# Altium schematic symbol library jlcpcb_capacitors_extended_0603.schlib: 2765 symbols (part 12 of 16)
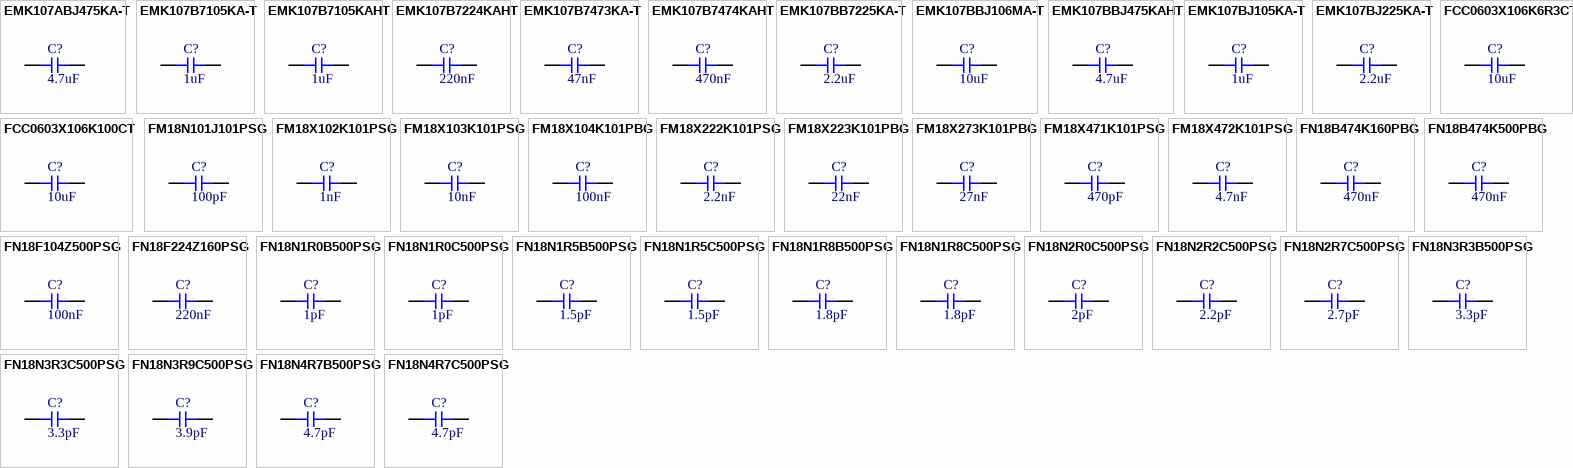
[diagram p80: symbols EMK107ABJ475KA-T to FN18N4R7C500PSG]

## FM18X471K101PSG
designator C?  Capacitance: 470pF  (hidden comment: *)
Capacitor, Ceramic (MLCC), 470pF, ±10%, 100V, X7R, ±10%, SMD 0603; Manufacturer: PSA(Prosperity Dielectrics); Manufacturer Part Number: FM18X471K101PSG
footprint CAP-0603 (0603 (1608M) Capacitor)
pins: 1, 2

## FM18X472K101PSG
designator C?  Capacitance: 4.7nF  (hidden comment: *)
Capacitor, Ceramic (MLCC), 4.7nF, ±10%, 100V, X7R, ±10%, SMD 0603; Manufacturer: PSA(Prosperity Dielectrics); Manufacturer Part Number: FM18X472K101PSG
footprint CAP-0603 (0603 (1608M) Capacitor)
pins: 1, 2

## FN18B474K160PBG
designator C?  Capacitance: 470nF  (hidden comment: *)
Capacitor, Ceramic (MLCC), 470nF, ±10%, 16V, X5R, ±10%, SMD 0603; Manufacturer: PSA(Prosperity Dielectrics); Manufacturer Part Number: FN18B474K160PBG
footprint CAP-0603 (0603 (1608M) Capacitor)
pins: 1, 2

## FN18B474K500PBG
designator C?  Capacitance: 470nF  (hidden comment: *)
Capacitor, Ceramic (MLCC), 470nF, ±10%, 50V, X5R, ±10%, SMD 0603; Manufacturer: PSA(Prosperity Dielectrics); Manufacturer Part Number: FN18B474K500PBG
footprint CAP-0603 (0603 (1608M) Capacitor)
pins: 1, 2

## FN18F104Z500PSG
designator C?  Capacitance: 100nF  (hidden comment: *)
Capacitor, Ceramic (MLCC), 100nF, 50V, Y5V, SMD 0603; Manufacturer: PSA(Prosperity Dielectrics); Manufacturer Part Number: FN18F104Z500PSG; Temperature Rating: -20%~+80%
footprint CAP-0603 (0603 (1608M) Capacitor)
pins: 1, 2

## FN18F224Z160PSG
designator C?  Capacitance: 220nF  (hidden comment: *)
Capacitor, Ceramic (MLCC), 220nF, 16V, Y5V, SMD 0603; Manufacturer: PSA(Prosperity Dielectrics); Manufacturer Part Number: FN18F224Z160PSG; Temperature Rating: -20%~+80%
footprint CAP-0603 (0603 (1608M) Capacitor)
pins: 1, 2

## FN18N1R0B500PSG
designator C?  Capacitance: 1pF  (hidden comment: *)
Capacitor, Ceramic (MLCC), 1pF, ±0.1pF, 50V, NP0, ±0.1pF, SMD 0603; Manufacturer: PSA(Prosperity Dielectrics); Manufacturer Part Number: FN18N1R0B500PSG
footprint CAP-0603 (0603 (1608M) Capacitor)
pins: 1, 2

## FN18N1R0C500PSG
designator C?  Capacitance: 1pF  (hidden comment: *)
Capacitor, Ceramic (MLCC), 1pF, ±0.25pF, 50V, C0G, ±0.25pF, SMD 0603; Manufacturer: PSA(Prosperity Dielectrics); Manufacturer Part Number: FN18N1R0C500PSG
footprint CAP-0603 (0603 (1608M) Capacitor)
pins: 1, 2

## FN18N1R5B500PSG
designator C?  Capacitance: 1.5pF  (hidden comment: *)
Capacitor, Ceramic (MLCC), 1.5pF, ±0.1pF, 50V, NP0, ±0.1pF, SMD 0603; Manufacturer: PSA(Prosperity Dielectrics); Manufacturer Part Number: FN18N1R5B500PSG
footprint CAP-0603 (0603 (1608M) Capacitor)
pins: 1, 2

## FN18N1R5C500PSG
designator C?  Capacitance: 1.5pF  (hidden comment: *)
Capacitor, Ceramic (MLCC), 1.5pF, ±0.25pF, 50V, C0G, ±0.25pF, SMD 0603; Manufacturer: PSA(Prosperity Dielectrics); Manufacturer Part Number: FN18N1R5C500PSG
footprint CAP-0603 (0603 (1608M) Capacitor)
pins: 1, 2

## FN18N1R8B500PSG
designator C?  Capacitance: 1.8pF  (hidden comment: *)
Capacitor, Ceramic (MLCC), 1.8pF, ±0.1pF, 50V, NP0, ±0.1pF, SMD 0603; Manufacturer: PSA(Prosperity Dielectrics); Manufacturer Part Number: FN18N1R8B500PSG
footprint CAP-0603 (0603 (1608M) Capacitor)
pins: 1, 2

## FN18N1R8C500PSG
designator C?  Capacitance: 1.8pF  (hidden comment: *)
Capacitor, Ceramic (MLCC), 1.8pF, ±0.25pF, 50V, C0G, ±0.25pF, SMD 0603; Manufacturer: PSA(Prosperity Dielectrics); Manufacturer Part Number: FN18N1R8C500PSG
footprint CAP-0603 (0603 (1608M) Capacitor)
pins: 1, 2

## FN18N2R0C500PSG
designator C?  Capacitance: 2pF  (hidden comment: *)
Capacitor, Ceramic (MLCC), 2pF, ±0.25pF, 50V, C0G, ±0.25pF, SMD 0603; Manufacturer: PSA(Prosperity Dielectrics); Manufacturer Part Number: FN18N2R0C500PSG
footprint CAP-0603 (0603 (1608M) Capacitor)
pins: 1, 2

## FN18N2R2C500PSG
designator C?  Capacitance: 2.2pF  (hidden comment: *)
Capacitor, Ceramic (MLCC), 2.2pF, ±0.25pF, 50V, NP0, ±0.25pF, SMD 0603; Manufacturer: PSA(Prosperity Dielectrics); Manufacturer Part Number: FN18N2R2C500PSG
footprint CAP-0603 (0603 (1608M) Capacitor)
pins: 1, 2

## FN18N2R7C500PSG
designator C?  Capacitance: 2.7pF  (hidden comment: *)
Capacitor, Ceramic (MLCC), 2.7pF, ±0.25pF, 50V, NP0, ±0.25pF, SMD 0603; Manufacturer: PSA(Prosperity Dielectrics); Manufacturer Part Number: FN18N2R7C500PSG
footprint CAP-0603 (0603 (1608M) Capacitor)
pins: 1, 2

## FN18N3R3B500PSG
designator C?  Capacitance: 3.3pF  (hidden comment: *)
Capacitor, Ceramic (MLCC), 3.3pF, ±0.1pF, 50V, NP0, ±0.1pF, SMD 0603; Manufacturer: PSA(Prosperity Dielectrics); Manufacturer Part Number: FN18N3R3B500PSG
footprint CAP-0603 (0603 (1608M) Capacitor)
pins: 1, 2

## FN18N3R3C500PSG
designator C?  Capacitance: 3.3pF  (hidden comment: *)
Capacitor, Ceramic (MLCC), 3.3pF, ±0.25pF, 50V, C0G, ±0.25pF, SMD 0603; Manufacturer: PSA(Prosperity Dielectrics); Manufacturer Part Number: FN18N3R3C500PSG
footprint CAP-0603 (0603 (1608M) Capacitor)
pins: 1, 2

## FN18N3R9C500PSG
designator C?  Capacitance: 3.9pF  (hidden comment: *)
Capacitor, Ceramic (MLCC), 3.9pF, ±0.25pF, 50V, C0G, ±0.25pF, SMD 0603; Manufacturer: PSA(Prosperity Dielectrics); Manufacturer Part Number: FN18N3R9C500PSG
footprint CAP-0603 (0603 (1608M) Capacitor)
pins: 1, 2

## FN18N4R7B500PSG
designator C?  Capacitance: 4.7pF  (hidden comment: *)
Capacitor, Ceramic (MLCC), 4.7pF, ±0.1pF, 50V, NP0, ±0.1pF, SMD 0603; Manufacturer: PSA(Prosperity Dielectrics); Manufacturer Part Number: FN18N4R7B500PSG
footprint CAP-0603 (0603 (1608M) Capacitor)
pins: 1, 2

## FN18N4R7C500PSG
designator C?  Capacitance: 4.7pF  (hidden comment: *)
Capacitor, Ceramic (MLCC), 4.7pF, ±0.25pF, 50V, C0G, ±0.25pF, SMD 0603; Manufacturer: PSA(Prosperity Dielectrics); Manufacturer Part Number: FN18N4R7C500PSG
footprint CAP-0603 (0603 (1608M) Capacitor)
pins: 1, 2

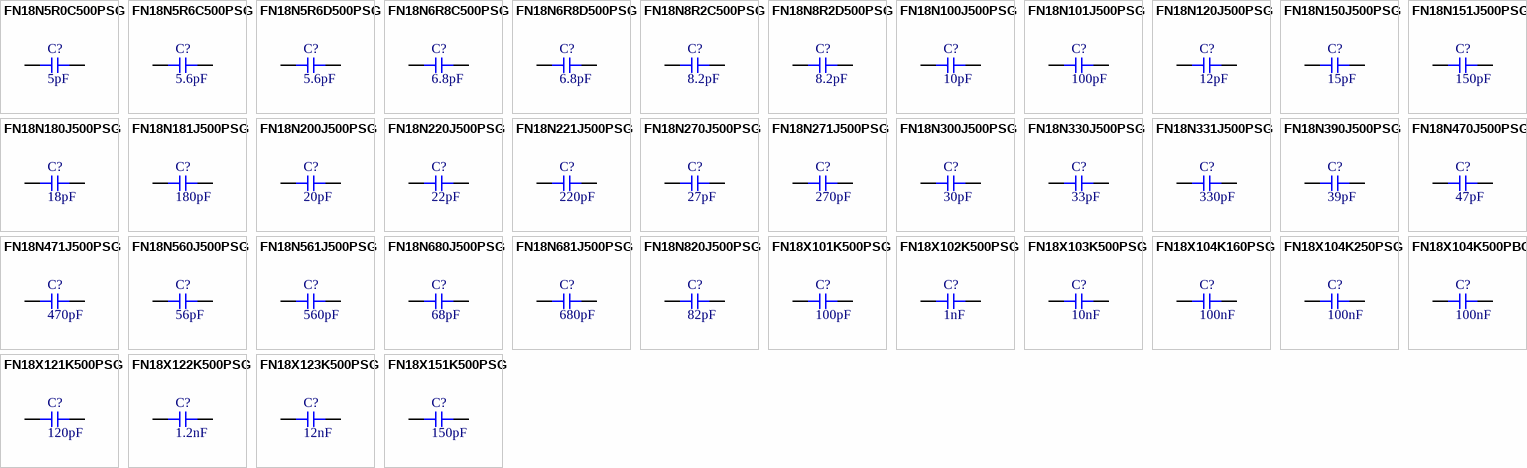
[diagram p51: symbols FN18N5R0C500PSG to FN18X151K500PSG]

## FN18N5R0C500PSG
designator C?  Capacitance: 5pF  (hidden comment: *)
Capacitor, Ceramic (MLCC), 5pF, ±0.25pF, 50V, C0G, ±0.25pF, SMD 0603; Manufacturer: PSA(Prosperity Dielectrics); Manufacturer Part Number: FN18N5R0C500PSG
footprint CAP-0603 (0603 (1608M) Capacitor)
pins: 1, 2

## FN18N5R6C500PSG
designator C?  Capacitance: 5.6pF  (hidden comment: *)
Capacitor, Ceramic (MLCC), 5.6pF, ±0.25pF, 50V, C0G, ±0.25pF, SMD 0603; Manufacturer: PSA(Prosperity Dielectrics); Manufacturer Part Number: FN18N5R6C500PSG
footprint CAP-0603 (0603 (1608M) Capacitor)
pins: 1, 2

## FN18N5R6D500PSG
designator C?  Capacitance: 5.6pF  (hidden comment: *)
Capacitor, Ceramic (MLCC), 5.6pF, ±0.5pF, 50V, C0G, ±0.5pF, SMD 0603; Manufacturer: PSA(Prosperity Dielectrics); Manufacturer Part Number: FN18N5R6D500PSG
footprint CAP-0603 (0603 (1608M) Capacitor)
pins: 1, 2

## FN18N6R8C500PSG
designator C?  Capacitance: 6.8pF  (hidden comment: *)
Capacitor, Ceramic (MLCC), 6.8pF, ±0.25pF, 50V, NP0, ±0.25pF, SMD 0603; Manufacturer: PSA(Prosperity Dielectrics); Manufacturer Part Number: FN18N6R8C500PSG
footprint CAP-0603 (0603 (1608M) Capacitor)
pins: 1, 2

## FN18N6R8D500PSG
designator C?  Capacitance: 6.8pF  (hidden comment: *)
Capacitor, Ceramic (MLCC), 6.8pF, ±0.5pF, 50V, C0G, ±0.5pF, SMD 0603; Manufacturer: PSA(Prosperity Dielectrics); Manufacturer Part Number: FN18N6R8D500PSG
footprint CAP-0603 (0603 (1608M) Capacitor)
pins: 1, 2

## FN18N8R2C500PSG
designator C?  Capacitance: 8.2pF  (hidden comment: *)
Capacitor, Ceramic (MLCC), 8.2pF, ±0.25pF, 50V, C0G, ±0.25pF, SMD 0603; Manufacturer: PSA(Prosperity Dielectrics); Manufacturer Part Number: FN18N8R2C500PSG
footprint CAP-0603 (0603 (1608M) Capacitor)
pins: 1, 2

## FN18N8R2D500PSG
designator C?  Capacitance: 8.2pF  (hidden comment: *)
Capacitor, Ceramic (MLCC), 8.2pF, ±0.5pF, 50V, C0G, ±0.5pF, SMD 0603; Manufacturer: PSA(Prosperity Dielectrics); Manufacturer Part Number: FN18N8R2D500PSG
footprint CAP-0603 (0603 (1608M) Capacitor)
pins: 1, 2

## FN18N100J500PSG
designator C?  Capacitance: 10pF  (hidden comment: *)
Capacitor, Ceramic (MLCC), 10pF, ±5%, 50V, NP0, ±5%, SMD 0603; Manufacturer: PSA(Prosperity Dielectrics); Manufacturer Part Number: FN18N100J500PSG
footprint CAP-0603 (0603 (1608M) Capacitor)
pins: 1, 2

## FN18N101J500PSG
designator C?  Capacitance: 100pF  (hidden comment: *)
Capacitor, Ceramic (MLCC), 100pF, ±5%, 50V, NP0, ±5%, SMD 0603; Manufacturer: PSA(Prosperity Dielectrics); Manufacturer Part Number: FN18N101J500PSG
footprint CAP-0603 (0603 (1608M) Capacitor)
pins: 1, 2

## FN18N120J500PSG
designator C?  Capacitance: 12pF  (hidden comment: *)
Capacitor, Ceramic (MLCC), 12pF, ±5%, 50V, C0G, ±5%, SMD 0603; Manufacturer: PSA(Prosperity Dielectrics); Manufacturer Part Number: FN18N120J500PSG
footprint CAP-0603 (0603 (1608M) Capacitor)
pins: 1, 2

## FN18N150J500PSG
designator C?  Capacitance: 15pF  (hidden comment: *)
Capacitor, Ceramic (MLCC), 15pF, ±5%, 50V, C0G, ±5%, SMD 0603; Manufacturer: PSA(Prosperity Dielectrics); Manufacturer Part Number: FN18N150J500PSG
footprint CAP-0603 (0603 (1608M) Capacitor)
pins: 1, 2

## FN18N151J500PSG
designator C?  Capacitance: 150pF  (hidden comment: *)
Capacitor, Ceramic (MLCC), 150pF, ±5%, 50V, NP0, ±5%, SMD 0603; Manufacturer: PSA(Prosperity Dielectrics); Manufacturer Part Number: FN18N151J500PSG
footprint CAP-0603 (0603 (1608M) Capacitor)
pins: 1, 2

## FN18N180J500PSG
designator C?  Capacitance: 18pF  (hidden comment: *)
Capacitor, Ceramic (MLCC), 18pF, ±5%, 50V, C0G, ±5%, SMD 0603; Manufacturer: PSA(Prosperity Dielectrics); Manufacturer Part Number: FN18N180J500PSG
footprint CAP-0603 (0603 (1608M) Capacitor)
pins: 1, 2

## FN18N181J500PSG
designator C?  Capacitance: 180pF  (hidden comment: *)
Capacitor, Ceramic (MLCC), 180pF, ±5%, 50V, C0G, ±5%, SMD 0603; Manufacturer: PSA(Prosperity Dielectrics); Manufacturer Part Number: FN18N181J500PSG
footprint CAP-0603 (0603 (1608M) Capacitor)
pins: 1, 2

## FN18N200J500PSG
designator C?  Capacitance: 20pF  (hidden comment: *)
Capacitor, Ceramic (MLCC), 20pF, ±5%, 50V, C0G, ±5%, SMD 0603; Manufacturer: PSA(Prosperity Dielectrics); Manufacturer Part Number: FN18N200J500PSG
footprint CAP-0603 (0603 (1608M) Capacitor)
pins: 1, 2

## FN18N220J500PSG
designator C?  Capacitance: 22pF  (hidden comment: *)
Capacitor, Ceramic (MLCC), 22pF, ±5%, 50V, C0G, ±5%, SMD 0603; Manufacturer: PSA(Prosperity Dielectrics); Manufacturer Part Number: FN18N220J500PSG
footprint CAP-0603 (0603 (1608M) Capacitor)
pins: 1, 2

## FN18N221J500PSG
designator C?  Capacitance: 220pF  (hidden comment: *)
Capacitor, Ceramic (MLCC), 220pF, ±5%, 50V, C0G, ±5%, SMD 0603; Manufacturer: PSA(Prosperity Dielectrics); Manufacturer Part Number: FN18N221J500PSG
footprint CAP-0603 (0603 (1608M) Capacitor)
pins: 1, 2

## FN18N270J500PSG
designator C?  Capacitance: 27pF  (hidden comment: *)
Capacitor, Ceramic (MLCC), 27pF, ±5%, 50V, C0G, ±5%, SMD 0603; Manufacturer: PSA(Prosperity Dielectrics); Manufacturer Part Number: FN18N270J500PSG
footprint CAP-0603 (0603 (1608M) Capacitor)
pins: 1, 2

## FN18N271J500PSG
designator C?  Capacitance: 270pF  (hidden comment: *)
Capacitor, Ceramic (MLCC), 270pF, ±5%, 50V, NP0, ±5%, SMD 0603; Manufacturer: PSA(Prosperity Dielectrics); Manufacturer Part Number: FN18N271J500PSG
footprint CAP-0603 (0603 (1608M) Capacitor)
pins: 1, 2

## FN18N300J500PSG
designator C?  Capacitance: 30pF  (hidden comment: *)
Capacitor, Ceramic (MLCC), 30pF, ±5%, 50V, C0G, ±5%, SMD 0603; Manufacturer: PSA(Prosperity Dielectrics); Manufacturer Part Number: FN18N300J500PSG
footprint CAP-0603 (0603 (1608M) Capacitor)
pins: 1, 2

## FN18N330J500PSG
designator C?  Capacitance: 33pF  (hidden comment: *)
Capacitor, Ceramic (MLCC), 33pF, ±5%, 50V, C0G, ±5%, SMD 0603; Manufacturer: PSA(Prosperity Dielectrics); Manufacturer Part Number: FN18N330J500PSG
footprint CAP-0603 (0603 (1608M) Capacitor)
pins: 1, 2

## FN18N331J500PSG
designator C?  Capacitance: 330pF  (hidden comment: *)
Capacitor, Ceramic (MLCC), 330pF, ±5%, 50V, C0G, ±5%, SMD 0603; Manufacturer: PSA(Prosperity Dielectrics); Manufacturer Part Number: FN18N331J500PSG
footprint CAP-0603 (0603 (1608M) Capacitor)
pins: 1, 2

## FN18N390J500PSG
designator C?  Capacitance: 39pF  (hidden comment: *)
Capacitor, Ceramic (MLCC), 39pF, ±5%, 50V, C0G, ±5%, SMD 0603; Manufacturer: PSA(Prosperity Dielectrics); Manufacturer Part Number: FN18N390J500PSG
footprint CAP-0603 (0603 (1608M) Capacitor)
pins: 1, 2

## FN18N470J500PSG
designator C?  Capacitance: 47pF  (hidden comment: *)
Capacitor, Ceramic (MLCC), 47pF, ±5%, 50V, C0G, ±5%, SMD 0603; Manufacturer: PSA(Prosperity Dielectrics); Manufacturer Part Number: FN18N470J500PSG
footprint CAP-0603 (0603 (1608M) Capacitor)
pins: 1, 2

## FN18N471J500PSG
designator C?  Capacitance: 470pF  (hidden comment: *)
Capacitor, Ceramic (MLCC), 470pF, ±5%, 50V, C0G, ±5%, SMD 0603; Manufacturer: PSA(Prosperity Dielectrics); Manufacturer Part Number: FN18N471J500PSG
footprint CAP-0603 (0603 (1608M) Capacitor)
pins: 1, 2

## FN18N560J500PSG
designator C?  Capacitance: 56pF  (hidden comment: *)
Capacitor, Ceramic (MLCC), 56pF, ±5%, 50V, C0G, ±5%, SMD 0603; Manufacturer: PSA(Prosperity Dielectrics); Manufacturer Part Number: FN18N560J500PSG
footprint CAP-0603 (0603 (1608M) Capacitor)
pins: 1, 2

## FN18N561J500PSG
designator C?  Capacitance: 560pF  (hidden comment: *)
Capacitor, Ceramic (MLCC), 560pF, ±5%, 50V, C0G, ±5%, SMD 0603; Manufacturer: PSA(Prosperity Dielectrics); Manufacturer Part Number: FN18N561J500PSG
footprint CAP-0603 (0603 (1608M) Capacitor)
pins: 1, 2

## FN18N680J500PSG
designator C?  Capacitance: 68pF  (hidden comment: *)
Capacitor, Ceramic (MLCC), 68pF, ±5%, 50V, C0G, ±5%, SMD 0603; Manufacturer: PSA(Prosperity Dielectrics); Manufacturer Part Number: FN18N680J500PSG
footprint CAP-0603 (0603 (1608M) Capacitor)
pins: 1, 2

## FN18N681J500PSG
designator C?  Capacitance: 680pF  (hidden comment: *)
Capacitor, Ceramic (MLCC), 680pF, ±5%, 50V, NP0, ±5%, SMD 0603; Manufacturer: PSA(Prosperity Dielectrics); Manufacturer Part Number: FN18N681J500PSG
footprint CAP-0603 (0603 (1608M) Capacitor)
pins: 1, 2

## FN18N820J500PSG
designator C?  Capacitance: 82pF  (hidden comment: *)
Capacitor, Ceramic (MLCC), 82pF, ±5%, 50V, C0G, ±5%, SMD 0603; Manufacturer: PSA(Prosperity Dielectrics); Manufacturer Part Number: FN18N820J500PSG
footprint CAP-0603 (0603 (1608M) Capacitor)
pins: 1, 2

## FN18X101K500PSG
designator C?  Capacitance: 100pF  (hidden comment: *)
Capacitor, Ceramic (MLCC), 100pF, ±10%, 50V, X7R, ±10%, SMD 0603; Manufacturer: PSA(Prosperity Dielectrics); Manufacturer Part Number: FN18X101K500PSG
footprint CAP-0603 (0603 (1608M) Capacitor)
pins: 1, 2

## FN18X102K500PSG
designator C?  Capacitance: 1nF  (hidden comment: *)
Capacitor, Ceramic (MLCC), 1nF, ±10%, 50V, X7R, ±10%, SMD 0603; Manufacturer: PSA(Prosperity Dielectrics); Manufacturer Part Number: FN18X102K500PSG
footprint CAP-0603 (0603 (1608M) Capacitor)
pins: 1, 2

## FN18X103K500PSG
designator C?  Capacitance: 10nF  (hidden comment: *)
Capacitor, Ceramic (MLCC), 10nF, ±10%, 50V, X7R, ±10%, SMD 0603; Manufacturer: PSA(Prosperity Dielectrics); Manufacturer Part Number: FN18X103K500PSG
footprint CAP-0603 (0603 (1608M) Capacitor)
pins: 1, 2

## FN18X104K160PSG
designator C?  Capacitance: 100nF  (hidden comment: *)
Capacitor, Ceramic (MLCC), 100nF, ±10%, 16V, X7R, ±10%, SMD 0603; Manufacturer: PSA(Prosperity Dielectrics); Manufacturer Part Number: FN18X104K160PSG
footprint CAP-0603 (0603 (1608M) Capacitor)
pins: 1, 2

## FN18X104K250PSG
designator C?  Capacitance: 100nF  (hidden comment: *)
Capacitor, Ceramic (MLCC), 100nF, ±10%, 25V, X7R, ±10%, SMD 0603; Manufacturer: PSA(Prosperity Dielectrics); Manufacturer Part Number: FN18X104K250PSG
footprint CAP-0603 (0603 (1608M) Capacitor)
pins: 1, 2

## FN18X104K500PBG
designator C?  Capacitance: 100nF  (hidden comment: *)
Capacitor, Ceramic (MLCC), 100nF, ±10%, 50V, X7R, ±10%, SMD 0603; Manufacturer: PSA(Prosperity Dielectrics); Manufacturer Part Number: FN18X104K500PBG
footprint CAP-0603 (0603 (1608M) Capacitor)
pins: 1, 2

## FN18X121K500PSG
designator C?  Capacitance: 120pF  (hidden comment: *)
Capacitor, Ceramic (MLCC), 120pF, ±10%, 50V, X7R, ±10%, SMD 0603; Manufacturer: PSA(Prosperity Dielectrics); Manufacturer Part Number: FN18X121K500PSG
footprint CAP-0603 (0603 (1608M) Capacitor)
pins: 1, 2

## FN18X122K500PSG
designator C?  Capacitance: 1.2nF  (hidden comment: *)
Capacitor, Ceramic (MLCC), 1.2nF, ±10%, 50V, X7R, ±10%, SMD 0603; Manufacturer: PSA(Prosperity Dielectrics); Manufacturer Part Number: FN18X122K500PSG
footprint CAP-0603 (0603 (1608M) Capacitor)
pins: 1, 2

## FN18X123K500PSG
designator C?  Capacitance: 12nF  (hidden comment: *)
Capacitor, Ceramic (MLCC), 12nF, ±10%, 50V, X7R, ±10%, SMD 0603; Manufacturer: PSA(Prosperity Dielectrics); Manufacturer Part Number: FN18X123K500PSG
footprint CAP-0603 (0603 (1608M) Capacitor)
pins: 1, 2

## FN18X151K500PSG
designator C?  Capacitance: 150pF  (hidden comment: *)
Capacitor, Ceramic (MLCC), 150pF, ±10%, 50V, X7R, ±10%, SMD 0603; Manufacturer: PSA(Prosperity Dielectrics); Manufacturer Part Number: FN18X151K500PSG
footprint CAP-0603 (0603 (1608M) Capacitor)
pins: 1, 2

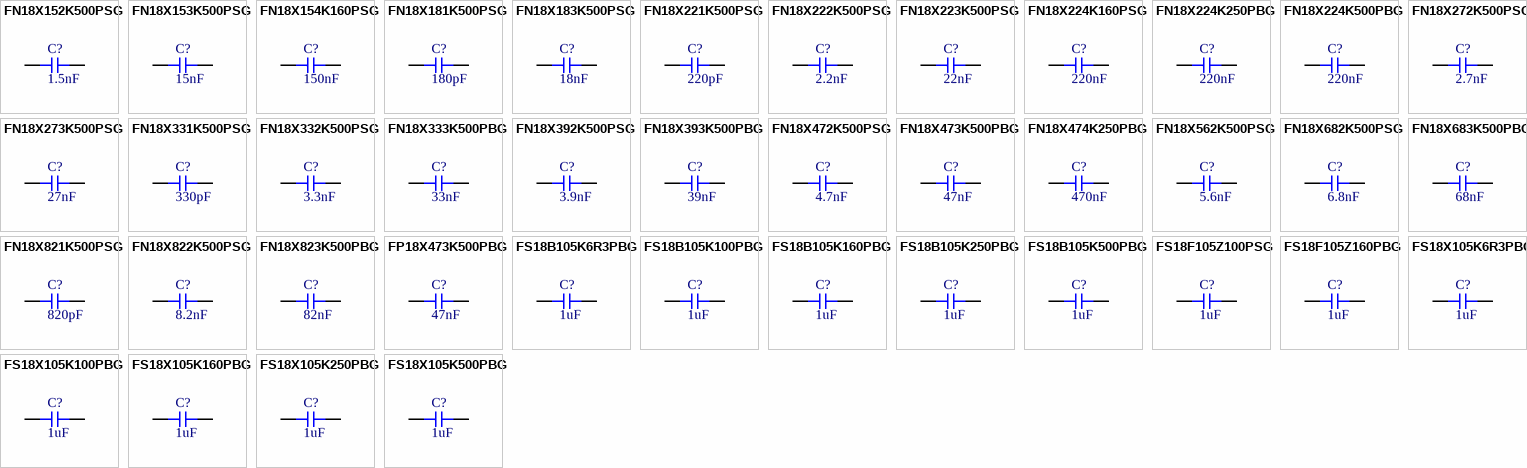
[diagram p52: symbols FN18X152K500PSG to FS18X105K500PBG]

## FN18X152K500PSG
designator C?  Capacitance: 1.5nF  (hidden comment: *)
Capacitor, Ceramic (MLCC), 1.5nF, ±10%, 50V, X7R, ±10%, SMD 0603; Manufacturer: PSA(Prosperity Dielectrics); Manufacturer Part Number: FN18X152K500PSG
footprint CAP-0603 (0603 (1608M) Capacitor)
pins: 1, 2

## FN18X153K500PSG
designator C?  Capacitance: 15nF  (hidden comment: *)
Capacitor, Ceramic (MLCC), 15nF, ±10%, 50V, X7R, ±10%, SMD 0603; Manufacturer: PSA(Prosperity Dielectrics); Manufacturer Part Number: FN18X153K500PSG
footprint CAP-0603 (0603 (1608M) Capacitor)
pins: 1, 2

## FN18X154K160PSG
designator C?  Capacitance: 150nF  (hidden comment: *)
Capacitor, Ceramic (MLCC), 150nF, ±10%, 16V, X7R, ±10%, SMD 0603; Manufacturer: PSA(Prosperity Dielectrics); Manufacturer Part Number: FN18X154K160PSG
footprint CAP-0603 (0603 (1608M) Capacitor)
pins: 1, 2

## FN18X181K500PSG
designator C?  Capacitance: 180pF  (hidden comment: *)
Capacitor, Ceramic (MLCC), 180pF, ±10%, 50V, X7R, ±10%, SMD 0603; Manufacturer: PSA(Prosperity Dielectrics); Manufacturer Part Number: FN18X181K500PSG
footprint CAP-0603 (0603 (1608M) Capacitor)
pins: 1, 2

## FN18X183K500PSG
designator C?  Capacitance: 18nF  (hidden comment: *)
Capacitor, Ceramic (MLCC), 18nF, ±10%, 50V, X7R, ±10%, SMD 0603; Manufacturer: PSA(Prosperity Dielectrics); Manufacturer Part Number: FN18X183K500PSG
footprint CAP-0603 (0603 (1608M) Capacitor)
pins: 1, 2

## FN18X221K500PSG
designator C?  Capacitance: 220pF  (hidden comment: *)
Capacitor, Ceramic (MLCC), 220pF, ±10%, 50V, X7R, ±10%, SMD 0603; Manufacturer: PSA(Prosperity Dielectrics); Manufacturer Part Number: FN18X221K500PSG
footprint CAP-0603 (0603 (1608M) Capacitor)
pins: 1, 2

## FN18X222K500PSG
designator C?  Capacitance: 2.2nF  (hidden comment: *)
Capacitor, Ceramic (MLCC), 2.2nF, ±10%, 50V, X7R, ±10%, SMD 0603; Manufacturer: PSA(Prosperity Dielectrics); Manufacturer Part Number: FN18X222K500PSG
footprint CAP-0603 (0603 (1608M) Capacitor)
pins: 1, 2

## FN18X223K500PSG
designator C?  Capacitance: 22nF  (hidden comment: *)
Capacitor, Ceramic (MLCC), 22nF, ±10%, 50V, X7R, ±10%, SMD 0603; Manufacturer: PSA(Prosperity Dielectrics); Manufacturer Part Number: FN18X223K500PSG
footprint CAP-0603 (0603 (1608M) Capacitor)
pins: 1, 2

## FN18X224K160PSG
designator C?  Capacitance: 220nF  (hidden comment: *)
Capacitor, Ceramic (MLCC), 220nF, ±10%, 16V, X7R, ±10%, SMD 0603; Manufacturer: PSA(Prosperity Dielectrics); Manufacturer Part Number: FN18X224K160PSG
footprint CAP-0603 (0603 (1608M) Capacitor)
pins: 1, 2

## FN18X224K250PBG
designator C?  Capacitance: 220nF  (hidden comment: *)
Capacitor, Ceramic (MLCC), 220nF, ±10%, 25V, X7R, ±10%, SMD 0603; Manufacturer: PSA(Prosperity Dielectrics); Manufacturer Part Number: FN18X224K250PBG
footprint CAP-0603 (0603 (1608M) Capacitor)
pins: 1, 2

## FN18X224K500PBG
designator C?  Capacitance: 220nF  (hidden comment: *)
Capacitor, Ceramic (MLCC), 220nF, ±10%, 50V, X7R, ±10%, SMD 0603; Manufacturer: PSA(Prosperity Dielectrics); Manufacturer Part Number: FN18X224K500PBG
footprint CAP-0603 (0603 (1608M) Capacitor)
pins: 1, 2

## FN18X272K500PSG
designator C?  Capacitance: 2.7nF  (hidden comment: *)
Capacitor, Ceramic (MLCC), 2.7nF, ±10%, 50V, X7R, ±10%, SMD 0603; Manufacturer: PSA(Prosperity Dielectrics); Manufacturer Part Number: FN18X272K500PSG
footprint CAP-0603 (0603 (1608M) Capacitor)
pins: 1, 2

## FN18X273K500PSG
designator C?  Capacitance: 27nF  (hidden comment: *)
Capacitor, Ceramic (MLCC), 27nF, ±10%, 50V, X7R, ±10%, SMD 0603; Manufacturer: PSA(Prosperity Dielectrics); Manufacturer Part Number: FN18X273K500PSG
footprint CAP-0603 (0603 (1608M) Capacitor)
pins: 1, 2

## FN18X331K500PSG
designator C?  Capacitance: 330pF  (hidden comment: *)
Capacitor, Ceramic (MLCC), 330pF, ±10%, 50V, X7R, ±10%, SMD 0603; Manufacturer: PSA(Prosperity Dielectrics); Manufacturer Part Number: FN18X331K500PSG
footprint CAP-0603 (0603 (1608M) Capacitor)
pins: 1, 2

## FN18X332K500PSG
designator C?  Capacitance: 3.3nF  (hidden comment: *)
Capacitor, Ceramic (MLCC), 3.3nF, ±10%, 50V, X7R, ±10%, SMD 0603; Manufacturer: PSA(Prosperity Dielectrics); Manufacturer Part Number: FN18X332K500PSG
footprint CAP-0603 (0603 (1608M) Capacitor)
pins: 1, 2

## FN18X333K500PBG
designator C?  Capacitance: 33nF  (hidden comment: *)
Capacitor, Ceramic (MLCC), 33nF, ±10%, 50V, X7R, ±10%, SMD 0603; Manufacturer: PSA(Prosperity Dielectrics); Manufacturer Part Number: FN18X333K500PBG
footprint CAP-0603 (0603 (1608M) Capacitor)
pins: 1, 2

## FN18X392K500PSG
designator C?  Capacitance: 3.9nF  (hidden comment: *)
Capacitor, Ceramic (MLCC), 3.9nF, ±10%, 50V, X7R, ±10%, SMD 0603; Manufacturer: PSA(Prosperity Dielectrics); Manufacturer Part Number: FN18X392K500PSG
footprint CAP-0603 (0603 (1608M) Capacitor)
pins: 1, 2

## FN18X393K500PBG
designator C?  Capacitance: 39nF  (hidden comment: *)
Capacitor, Ceramic (MLCC), 39nF, ±10%, 50V, X7R, ±10%, SMD 0603; Manufacturer: PSA(Prosperity Dielectrics); Manufacturer Part Number: FN18X393K500PBG
footprint CAP-0603 (0603 (1608M) Capacitor)
pins: 1, 2

## FN18X472K500PSG
designator C?  Capacitance: 4.7nF  (hidden comment: *)
Capacitor, Ceramic (MLCC), 4.7nF, ±10%, 50V, X7R, ±10%, SMD 0603; Manufacturer: PSA(Prosperity Dielectrics); Manufacturer Part Number: FN18X472K500PSG
footprint CAP-0603 (0603 (1608M) Capacitor)
pins: 1, 2

## FN18X473K500PBG
designator C?  Capacitance: 47nF  (hidden comment: *)
Capacitor, Ceramic (MLCC), 47nF, ±10%, 50V, X7R, ±10%, SMD 0603; Manufacturer: PSA(Prosperity Dielectrics); Manufacturer Part Number: FN18X473K500PBG
footprint CAP-0603 (0603 (1608M) Capacitor)
pins: 1, 2

## FN18X474K250PBG
designator C?  Capacitance: 470nF  (hidden comment: *)
Capacitor, Ceramic (MLCC), 470nF, ±10%, 25V, X7R, ±10%, SMD 0603; Manufacturer: PSA(Prosperity Dielectrics); Manufacturer Part Number: FN18X474K250PBG
footprint CAP-0603 (0603 (1608M) Capacitor)
pins: 1, 2

## FN18X562K500PSG
designator C?  Capacitance: 5.6nF  (hidden comment: *)
Capacitor, Ceramic (MLCC), 5.6nF, ±10%, 50V, X7R, ±10%, SMD 0603; Manufacturer: PSA(Prosperity Dielectrics); Manufacturer Part Number: FN18X562K500PSG
footprint CAP-0603 (0603 (1608M) Capacitor)
pins: 1, 2

## FN18X682K500PSG
designator C?  Capacitance: 6.8nF  (hidden comment: *)
Capacitor, Ceramic (MLCC), 6.8nF, ±10%, 50V, X7R, ±10%, SMD 0603; Manufacturer: PSA(Prosperity Dielectrics); Manufacturer Part Number: FN18X682K500PSG
footprint CAP-0603 (0603 (1608M) Capacitor)
pins: 1, 2

## FN18X683K500PBG
designator C?  Capacitance: 68nF  (hidden comment: *)
Capacitor, Ceramic (MLCC), 68nF, ±10%, 50V, X7R, ±10%, SMD 0603; Manufacturer: PSA(Prosperity Dielectrics); Manufacturer Part Number: FN18X683K500PBG
footprint CAP-0603 (0603 (1608M) Capacitor)
pins: 1, 2

## FN18X821K500PSG
designator C?  Capacitance: 820pF  (hidden comment: *)
Capacitor, Ceramic (MLCC), 820pF, ±10%, 50V, X7R, ±10%, SMD 0603; Manufacturer: PSA(Prosperity Dielectrics); Manufacturer Part Number: FN18X821K500PSG
footprint CAP-0603 (0603 (1608M) Capacitor)
pins: 1, 2

## FN18X822K500PSG
designator C?  Capacitance: 8.2nF  (hidden comment: *)
Capacitor, Ceramic (MLCC), 8.2nF, ±10%, 50V, X7R, ±10%, SMD 0603; Manufacturer: PSA(Prosperity Dielectrics); Manufacturer Part Number: FN18X822K500PSG
footprint CAP-0603 (0603 (1608M) Capacitor)
pins: 1, 2

## FN18X823K500PBG
designator C?  Capacitance: 82nF  (hidden comment: *)
Capacitor, Ceramic (MLCC), 82nF, ±10%, 50V, X7R, ±10%, SMD 0603; Manufacturer: PSA(Prosperity Dielectrics); Manufacturer Part Number: FN18X823K500PBG
footprint CAP-0603 (0603 (1608M) Capacitor)
pins: 1, 2

## FP18X473K500PBG
designator C?  Capacitance: 47nF  (hidden comment: *)
Capacitor, Ceramic (MLCC), 47nF, ±10%, 50V, X7R, ±10%, SMD 0603; Manufacturer: PSA(Prosperity Dielectrics); Manufacturer Part Number: FP18X473K500PBG
footprint CAP-0603 (0603 (1608M) Capacitor)
pins: 1, 2

## FS18B105K6R3PBG
designator C?  Capacitance: 1uF  (hidden comment: *)
Capacitor, Ceramic (MLCC), 1uF, ±10%, 6.3V, X5R, ±10%, SMD 0603; Manufacturer: PSA(Prosperity Dielectrics); Manufacturer Part Number: FS18B105K6R3PBG
footprint CAP-0603 (0603 (1608M) Capacitor)
pins: 1, 2

## FS18B105K100PBG
designator C?  Capacitance: 1uF  (hidden comment: *)
Capacitor, Ceramic (MLCC), 1uF, ±10%, 10V, X5R, ±10%, SMD 0603; Manufacturer: PSA(Prosperity Dielectrics); Manufacturer Part Number: FS18B105K100PBG
footprint CAP-0603 (0603 (1608M) Capacitor)
pins: 1, 2

## FS18B105K160PBG
designator C?  Capacitance: 1uF  (hidden comment: *)
Capacitor, Ceramic (MLCC), 1uF, ±10%, 16V, X5R, ±10%, SMD 0603; Manufacturer: PSA(Prosperity Dielectrics); Manufacturer Part Number: FS18B105K160PBG
footprint CAP-0603 (0603 (1608M) Capacitor)
pins: 1, 2

## FS18B105K250PBG
designator C?  Capacitance: 1uF  (hidden comment: *)
Capacitor, Ceramic (MLCC), 1uF, ±10%, 25V, X5R, ±10%, SMD 0603; Manufacturer: PSA(Prosperity Dielectrics); Manufacturer Part Number: FS18B105K250PBG
footprint CAP-0603 (0603 (1608M) Capacitor)
pins: 1, 2

## FS18B105K500PBG
designator C?  Capacitance: 1uF  (hidden comment: *)
Capacitor, Ceramic (MLCC), 1uF, ±10%, 50V, X5R, ±10%, SMD 0603; Manufacturer: PSA(Prosperity Dielectrics); Manufacturer Part Number: FS18B105K500PBG
footprint CAP-0603 (0603 (1608M) Capacitor)
pins: 1, 2

## FS18F105Z100PSG
designator C?  Capacitance: 1uF  (hidden comment: *)
Capacitor, Ceramic (MLCC), 1uF, 10V, Y5V, SMD 0603; Manufacturer: PSA(Prosperity Dielectrics); Manufacturer Part Number: FS18F105Z100PSG; Temperature Rating: -20%~+80%
footprint CAP-0603 (0603 (1608M) Capacitor)
pins: 1, 2

## FS18F105Z160PBG
designator C?  Capacitance: 1uF  (hidden comment: *)
Capacitor, Ceramic (MLCC), 1uF, 16V, Y5V, SMD 0603; Manufacturer: PSA(Prosperity Dielectrics); Manufacturer Part Number: FS18F105Z160PBG; Temperature Rating: -20%~+80%
footprint CAP-0603 (0603 (1608M) Capacitor)
pins: 1, 2

## FS18X105K6R3PBG
designator C?  Capacitance: 1uF  (hidden comment: *)
Capacitor, Ceramic (MLCC), 1uF, ±10%, 6.3V, X7R, ±10%, SMD 0603; Manufacturer: PSA(Prosperity Dielectrics); Manufacturer Part Number: FS18X105K6R3PBG
footprint CAP-0603 (0603 (1608M) Capacitor)
pins: 1, 2

## FS18X105K100PBG
designator C?  Capacitance: 1uF  (hidden comment: *)
Capacitor, Ceramic (MLCC), 1uF, ±10%, 10V, X7R, ±10%, SMD 0603; Manufacturer: PSA(Prosperity Dielectrics); Manufacturer Part Number: FS18X105K100PBG
footprint CAP-0603 (0603 (1608M) Capacitor)
pins: 1, 2

## FS18X105K160PBG
designator C?  Capacitance: 1uF  (hidden comment: *)
Capacitor, Ceramic (MLCC), 1uF, ±10%, 16V, X7R, ±10%, SMD 0603; Manufacturer: PSA(Prosperity Dielectrics); Manufacturer Part Number: FS18X105K160PBG
footprint CAP-0603 (0603 (1608M) Capacitor)
pins: 1, 2

## FS18X105K250PBG
designator C?  Capacitance: 1uF  (hidden comment: *)
Capacitor, Ceramic (MLCC), 1uF, ±10%, 25V, X7R, ±10%, SMD 0603; Manufacturer: PSA(Prosperity Dielectrics); Manufacturer Part Number: FS18X105K250PBG
footprint CAP-0603 (0603 (1608M) Capacitor)
pins: 1, 2

## FS18X105K500PBG
designator C?  Capacitance: 1uF  (hidden comment: *)
Capacitor, Ceramic (MLCC), 1uF, ±10%, 50V, X7R, ±10%, SMD 0603; Manufacturer: PSA(Prosperity Dielectrics); Manufacturer Part Number: FS18X105K500PBG
footprint CAP-0603 (0603 (1608M) Capacitor)
pins: 1, 2

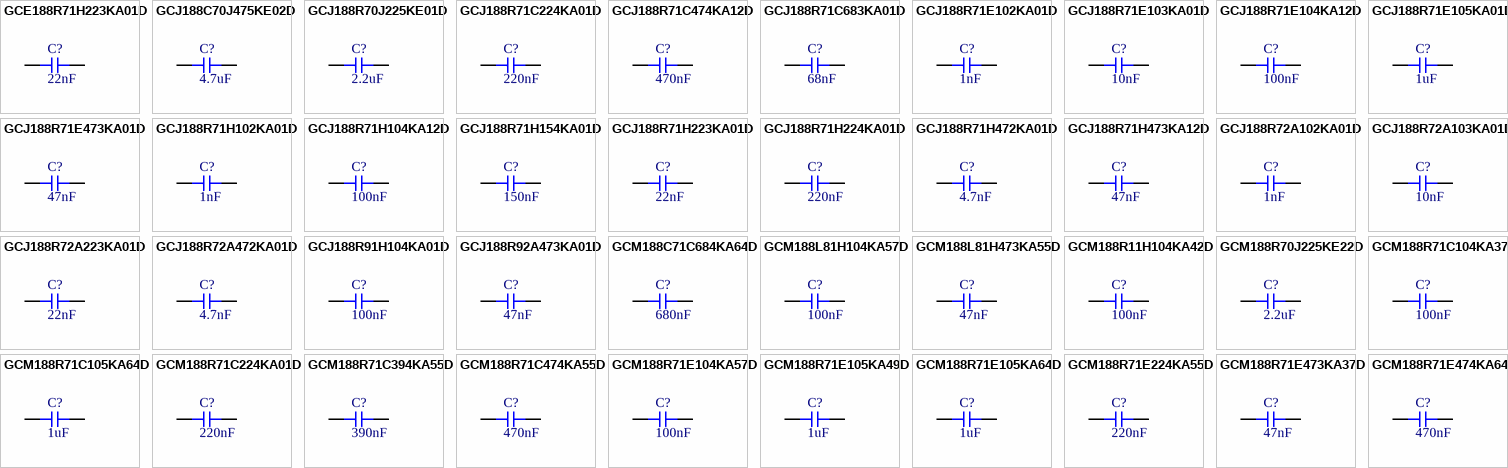
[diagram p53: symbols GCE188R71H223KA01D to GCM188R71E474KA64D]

## GCE188R71H223KA01D
designator C?  Capacitance: 22nF  (hidden comment: *)
Capacitor, Ceramic (MLCC), 22nF, ±10%, 50V, X7R, ±10%, SMD 0603; Manufacturer: Murata Electronics; Manufacturer Part Number: GCE188R71H223KA01D
footprint CAP-0603 (0603 (1608M) Capacitor)
pins: 1, 2

## GCJ188C70J475KE02D
designator C?  Capacitance: 4.7uF  (hidden comment: *)
Capacitor, Ceramic (MLCC), 4.7uF, ±10%, 6.3V, X7S, ±10%, SMD 0603; Manufacturer: Murata Electronics; Manufacturer Part Number: GCJ188C70J475KE02D
footprint CAP-0603 (0603 (1608M) Capacitor)
pins: 1, 2

## GCJ188R70J225KE01D
designator C?  Capacitance: 2.2uF  (hidden comment: *)
Capacitor, Ceramic (MLCC), 2.2uF, ±10%, ±10%, SMD 0603; Manufacturer: Murata Electronics; Manufacturer Part Number: GCJ188R70J225KE01D
footprint CAP-0603 (0603 (1608M) Capacitor)
pins: 1, 2

## GCJ188R71C224KA01D
designator C?  Capacitance: 220nF  (hidden comment: *)
Capacitor, Ceramic (MLCC), 220nF, ±10%, ±10%, SMD 0603; Manufacturer: Murata Electronics; Manufacturer Part Number: GCJ188R71C224KA01D
footprint CAP-0603 (0603 (1608M) Capacitor)
pins: 1, 2

## GCJ188R71C474KA12D
designator C?  Capacitance: 470nF  (hidden comment: *)
Capacitor, Ceramic (MLCC), 470nF, ±10%, 16V, X7R, ±10%, SMD 0603; Manufacturer: Murata Electronics; Manufacturer Part Number: GCJ188R71C474KA12D
footprint CAP-0603 (0603 (1608M) Capacitor)
pins: 1, 2

## GCJ188R71C683KA01D
designator C?  Capacitance: 68nF  (hidden comment: *)
Capacitor, Ceramic (MLCC), 68nF, ±10%, 16V, X7R, ±10%, SMD 0603; Manufacturer: Murata Electronics; Manufacturer Part Number: GCJ188R71C683KA01D
footprint CAP-0603 (0603 (1608M) Capacitor)
pins: 1, 2

## GCJ188R71E102KA01D
designator C?  Capacitance: 1nF  (hidden comment: *)
Capacitor, Ceramic (MLCC), 1nF, ±10%, 25V, X7R, ±10%, SMD 0603; Manufacturer: Murata Electronics; Manufacturer Part Number: GCJ188R71E102KA01D
footprint CAP-0603 (0603 (1608M) Capacitor)
pins: 1, 2

## GCJ188R71E103KA01D
designator C?  Capacitance: 10nF  (hidden comment: *)
Capacitor, Ceramic (MLCC), 10nF, ±10%, 25V, X7R, ±10%, SMD 0603; Manufacturer: Murata Electronics; Manufacturer Part Number: GCJ188R71E103KA01D
footprint CAP-0603 (0603 (1608M) Capacitor)
pins: 1, 2

## GCJ188R71E104KA12D
designator C?  Capacitance: 100nF  (hidden comment: *)
Capacitor, Ceramic (MLCC), 100nF, ±10%, 25V, X7R, ±10%, SMD 0603; Manufacturer: Murata Electronics; Manufacturer Part Number: GCJ188R71E104KA12D
footprint CAP-0603 (0603 (1608M) Capacitor)
pins: 1, 2

## GCJ188R71E105KA01D
designator C?  Capacitance: 1uF  (hidden comment: *)
Capacitor, Ceramic (MLCC), 1uF, ±10%, ±10%, SMD 0603; Manufacturer: Murata Electronics; Manufacturer Part Number: GCJ188R71E105KA01D
footprint CAP-0603 (0603 (1608M) Capacitor)
pins: 1, 2

## GCJ188R71E473KA01D
designator C?  Capacitance: 47nF  (hidden comment: *)
Capacitor, Ceramic (MLCC), 47nF, ±10%, 25V, X7R, ±10%, SMD 0603; Manufacturer: Murata Electronics; Manufacturer Part Number: GCJ188R71E473KA01D
footprint CAP-0603 (0603 (1608M) Capacitor)
pins: 1, 2

## GCJ188R71H102KA01D
designator C?  Capacitance: 1nF  (hidden comment: *)
Capacitor, Ceramic (MLCC), 1nF, ±10%, 50V, X7R, ±10%, SMD 0603; Manufacturer: Murata Electronics; Manufacturer Part Number: GCJ188R71H102KA01D
footprint CAP-0603 (0603 (1608M) Capacitor)
pins: 1, 2

## GCJ188R71H104KA12D
designator C?  Capacitance: 100nF  (hidden comment: *)
Capacitor, Ceramic (MLCC), 100nF, ±10%, 50V, X7R, ±10%, SMD 0603; Manufacturer: Murata Electronics; Manufacturer Part Number: GCJ188R71H104KA12D
footprint CAP-0603 (0603 (1608M) Capacitor)
pins: 1, 2

## GCJ188R71H154KA01D
designator C?  Capacitance: 150nF  (hidden comment: *)
Capacitor, Ceramic (MLCC), 150nF, ±10%, 50V, X7R, ±10%, SMD 0603; Manufacturer: Murata Electronics; Manufacturer Part Number: GCJ188R71H154KA01D
footprint CAP-0603 (0603 (1608M) Capacitor)
pins: 1, 2

## GCJ188R71H223KA01D
designator C?  Capacitance: 22nF  (hidden comment: *)
Capacitor, Ceramic (MLCC), 22nF, ±10%, 50V, X7R, ±10%, SMD 0603; Manufacturer: Murata Electronics; Manufacturer Part Number: GCJ188R71H223KA01D
footprint CAP-0603 (0603 (1608M) Capacitor)
pins: 1, 2

## GCJ188R71H224KA01D
designator C?  Capacitance: 220nF  (hidden comment: *)
Capacitor, Ceramic (MLCC), 220nF, ±10%, 50V, X7R, ±10%, SMD 0603; Manufacturer: Murata Electronics; Manufacturer Part Number: GCJ188R71H224KA01D
footprint CAP-0603 (0603 (1608M) Capacitor)
pins: 1, 2

## GCJ188R71H472KA01D
designator C?  Capacitance: 4.7nF  (hidden comment: *)
Capacitor, Ceramic (MLCC), 4.7nF, ±10%, 50V, X7R, ±10%, SMD 0603; Manufacturer: Murata Electronics; Manufacturer Part Number: GCJ188R71H472KA01D
footprint CAP-0603 (0603 (1608M) Capacitor)
pins: 1, 2

## GCJ188R71H473KA12D
designator C?  Capacitance: 47nF  (hidden comment: *)
Capacitor, Ceramic (MLCC), 47nF, ±10%, 50V, X7R, ±10%, SMD 0603; Manufacturer: Murata Electronics; Manufacturer Part Number: GCJ188R71H473KA12D
footprint CAP-0603 (0603 (1608M) Capacitor)
pins: 1, 2

## GCJ188R72A102KA01D
designator C?  Capacitance: 1nF  (hidden comment: *)
Capacitor, Ceramic (MLCC), 1nF, ±10%, 100V, X7R, ±10%, SMD 0603; Manufacturer: Murata Electronics; Manufacturer Part Number: GCJ188R72A102KA01D
footprint CAP-0603 (0603 (1608M) Capacitor)
pins: 1, 2

## GCJ188R72A103KA01D
designator C?  Capacitance: 10nF  (hidden comment: *)
Capacitor, Ceramic (MLCC), 10nF, ±10%, 100V, X7R, ±10%, SMD 0603; Manufacturer: Murata Electronics; Manufacturer Part Number: GCJ188R72A103KA01D
footprint CAP-0603 (0603 (1608M) Capacitor)
pins: 1, 2

## GCJ188R72A223KA01D
designator C?  Capacitance: 22nF  (hidden comment: *)
Capacitor, Ceramic (MLCC), 22nF, ±10%, 100V, X7R, ±10%, SMD 0603; Manufacturer: Murata Electronics; Manufacturer Part Number: GCJ188R72A223KA01D
footprint CAP-0603 (0603 (1608M) Capacitor)
pins: 1, 2

## GCJ188R72A472KA01D
designator C?  Capacitance: 4.7nF  (hidden comment: *)
Capacitor, Ceramic (MLCC), 4.7nF, ±10%, 100V, X7R, ±10%, SMD 0603; Manufacturer: Murata Electronics; Manufacturer Part Number: GCJ188R72A472KA01D
footprint CAP-0603 (0603 (1608M) Capacitor)
pins: 1, 2

## GCJ188R91H104KA01D
designator C?  Capacitance: 100nF  (hidden comment: *)
Capacitor, Ceramic (MLCC), 100nF, ±10%, ±10%, SMD 0603; Manufacturer: Murata Electronics; Manufacturer Part Number: GCJ188R91H104KA01D
footprint CAP-0603 (0603 (1608M) Capacitor)
pins: 1, 2

## GCJ188R92A473KA01D
designator C?  Capacitance: 47nF  (hidden comment: *)
Capacitor, Ceramic (MLCC), 47nF, ±10%, 100V, X8R, ±10%, SMD 0603; Manufacturer: Murata Electronics; Manufacturer Part Number: GCJ188R92A473KA01D
footprint CAP-0603 (0603 (1608M) Capacitor)
pins: 1, 2

## GCM188C71C684KA64D
designator C?  Capacitance: 680nF  (hidden comment: *)
Capacitor, Ceramic (MLCC), 680nF, ±10%, 16V, X7S, ±10%, SMD 0603; Manufacturer: Murata Electronics; Manufacturer Part Number: GCM188C71C684KA64D
footprint CAP-0603 (0603 (1608M) Capacitor)
pins: 1, 2

## GCM188L81H104KA57D
designator C?  Capacitance: 100nF  (hidden comment: *)
Capacitor, Ceramic (MLCC), 100nF, ±10%, 50V, X8L, ±10%, SMD 0603; Manufacturer: Murata Electronics; Manufacturer Part Number: GCM188L81H104KA57D
footprint CAP-0603 (0603 (1608M) Capacitor)
pins: 1, 2

## GCM188L81H473KA55D
designator C?  Capacitance: 47nF  (hidden comment: *)
Capacitor, Ceramic (MLCC), 47nF, ±10%, 50V, X8L, ±10%, SMD 0603; Manufacturer: Murata Electronics; Manufacturer Part Number: GCM188L81H473KA55D
footprint CAP-0603 (0603 (1608M) Capacitor)
pins: 1, 2

## GCM188R11H104KA42D
designator C?  Capacitance: 100nF  (hidden comment: *)
Capacitor, Ceramic (MLCC), 100nF, ±10%, ±10%, SMD 0603; Manufacturer: Murata Electronics; Manufacturer Part Number: GCM188R11H104KA42D
footprint CAP-0603 (0603 (1608M) Capacitor)
pins: 1, 2

## GCM188R70J225KE22D
designator C?  Capacitance: 2.2uF  (hidden comment: *)
Capacitor, Ceramic (MLCC), 2.2uF, ±10%, 6.3V, X7R, ±10%, SMD 0603; Manufacturer: Murata Electronics; Manufacturer Part Number: GCM188R70J225KE22D
footprint CAP-0603 (0603 (1608M) Capacitor)
pins: 1, 2

## GCM188R71C104KA37D
designator C?  Capacitance: 100nF  (hidden comment: *)
Capacitor, Ceramic (MLCC), 100nF, ±10%, 16V, X7R, ±10%, SMD 0603; Manufacturer: Murata Electronics; Manufacturer Part Number: GCM188R71C104KA37D
footprint CAP-0603 (0603 (1608M) Capacitor)
pins: 1, 2

## GCM188R71C105KA64D
designator C?  Capacitance: 1uF  (hidden comment: *)
Capacitor, Ceramic (MLCC), 1uF, ±10%, 16V, X7R, ±10%, SMD 0603; Manufacturer: Murata Electronics; Manufacturer Part Number: GCM188R71C105KA64D
footprint CAP-0603 (0603 (1608M) Capacitor)
pins: 1, 2

## GCM188R71C224KA01D
designator C?  Capacitance: 220nF  (hidden comment: *)
Capacitor, Ceramic (MLCC), 220nF, ±10%, 16V, X7R, ±10%, SMD 0603; Manufacturer: Murata Electronics; Manufacturer Part Number: GCM188R71C224KA01D
footprint CAP-0603 (0603 (1608M) Capacitor)
pins: 1, 2

## GCM188R71C394KA55D
designator C?  Capacitance: 390nF  (hidden comment: *)
Capacitor, Ceramic (MLCC), 390nF, ±10%, 16V, X7R, ±10%, SMD 0603; Manufacturer: Murata Electronics; Manufacturer Part Number: GCM188R71C394KA55D
footprint CAP-0603 (0603 (1608M) Capacitor)
pins: 1, 2

## GCM188R71C474KA55D
designator C?  Capacitance: 470nF  (hidden comment: *)
Capacitor, Ceramic (MLCC), 470nF, ±10%, 16V, X7R, ±10%, SMD 0603; Manufacturer: Murata Electronics; Manufacturer Part Number: GCM188R71C474KA55D
footprint CAP-0603 (0603 (1608M) Capacitor)
pins: 1, 2

## GCM188R71E104KA57D
designator C?  Capacitance: 100nF  (hidden comment: *)
Capacitor, Ceramic (MLCC), 100nF, ±10%, 25V, X7R, ±10%, SMD 0603; Manufacturer: Murata Electronics; Manufacturer Part Number: GCM188R71E104KA57D
footprint CAP-0603 (0603 (1608M) Capacitor)
pins: 1, 2

## GCM188R71E105KA49D
designator C?  Capacitance: 1uF  (hidden comment: *)
Capacitor, Ceramic (MLCC), 1uF, ±10%, 25V, ±10%, SMD 0603; Manufacturer: Murata Electronics; Manufacturer Part Number: GCM188R71E105KA49D
footprint CAP-0603 (0603 (1608M) Capacitor)
pins: 1, 2

## GCM188R71E105KA64D
designator C?  Capacitance: 1uF  (hidden comment: *)
Capacitor, Ceramic (MLCC), 1uF, ±10%, 25V, X7R, ±10%, SMD 0603; Manufacturer: Murata Electronics; Manufacturer Part Number: GCM188R71E105KA64D
footprint CAP-0603 (0603 (1608M) Capacitor)
pins: 1, 2

## GCM188R71E224KA55D
designator C?  Capacitance: 220nF  (hidden comment: *)
Capacitor, Ceramic (MLCC), 220nF, ±10%, 25V, X7R, ±10%, SMD 0603; Manufacturer: Murata Electronics; Manufacturer Part Number: GCM188R71E224KA55D
footprint CAP-0603 (0603 (1608M) Capacitor)
pins: 1, 2

## GCM188R71E473KA37D
designator C?  Capacitance: 47nF  (hidden comment: *)
Capacitor, Ceramic (MLCC), 47nF, ±10%, 25V, X7R, ±10%, SMD 0603; Manufacturer: Murata Electronics; Manufacturer Part Number: GCM188R71E473KA37D
footprint CAP-0603 (0603 (1608M) Capacitor)
pins: 1, 2

## GCM188R71E474KA64D
designator C?  Capacitance: 470nF  (hidden comment: *)
Capacitor, Ceramic (MLCC), 470nF, ±10%, 25V, X7R, ±10%, SMD 0603; Manufacturer: Murata Electronics; Manufacturer Part Number: GCM188R71E474KA64D
footprint CAP-0603 (0603 (1608M) Capacitor)
pins: 1, 2

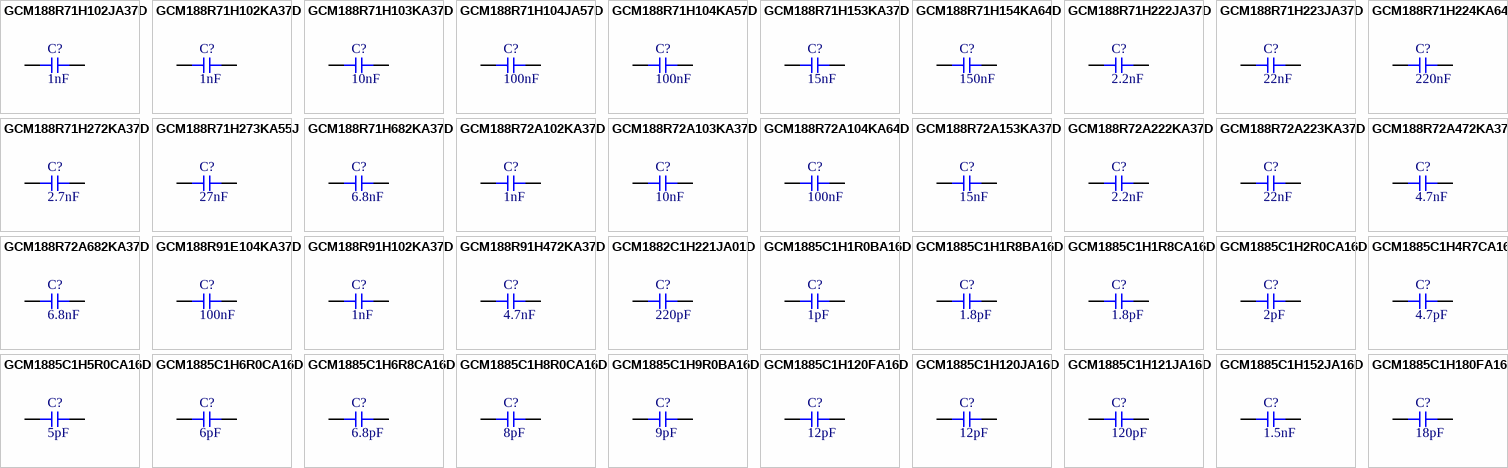
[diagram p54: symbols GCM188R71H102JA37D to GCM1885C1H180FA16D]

## GCM188R71H102JA37D
designator C?  Capacitance: 1nF  (hidden comment: *)
Capacitor, Ceramic (MLCC), 1nF, ±5%, 50V, X7R, ±5%, SMD 0603; Manufacturer: Murata Electronics; Manufacturer Part Number: GCM188R71H102JA37D
footprint CAP-0603 (0603 (1608M) Capacitor)
pins: 1, 2

## GCM188R71H102KA37D
designator C?  Capacitance: 1nF  (hidden comment: *)
Capacitor, Ceramic (MLCC), 1nF, ±10%, 50V, X7R, ±10%, SMD 0603; Manufacturer: Murata Electronics; Manufacturer Part Number: GCM188R71H102KA37D
footprint CAP-0603 (0603 (1608M) Capacitor)
pins: 1, 2

## GCM188R71H103KA37D
designator C?  Capacitance: 10nF  (hidden comment: *)
Capacitor, Ceramic (MLCC), 10nF, ±10%, 50V, X7R, ±10%, SMD 0603; Manufacturer: Murata Electronics; Manufacturer Part Number: GCM188R71H103KA37D
footprint CAP-0603 (0603 (1608M) Capacitor)
pins: 1, 2

## GCM188R71H104JA57D
designator C?  Capacitance: 100nF  (hidden comment: *)
Capacitor, Ceramic (MLCC), 100nF, ±5%, 50V, X7R, ±5%, SMD 0603; Manufacturer: Murata Electronics; Manufacturer Part Number: GCM188R71H104JA57D
footprint CAP-0603 (0603 (1608M) Capacitor)
pins: 1, 2

## GCM188R71H104KA57D
designator C?  Capacitance: 100nF  (hidden comment: *)
Capacitor, Ceramic (MLCC), 100nF, ±10%, 50V, X7R, ±10%, SMD 0603; Manufacturer: Murata Electronics; Manufacturer Part Number: GCM188R71H104KA57D
footprint CAP-0603 (0603 (1608M) Capacitor)
pins: 1, 2

## GCM188R71H153KA37D
designator C?  Capacitance: 15nF  (hidden comment: *)
Capacitor, Ceramic (MLCC), 15nF, ±10%, 50V, X7R, ±10%, SMD 0603; Manufacturer: Murata Electronics; Manufacturer Part Number: GCM188R71H153KA37D
footprint CAP-0603 (0603 (1608M) Capacitor)
pins: 1, 2

## GCM188R71H154KA64D
designator C?  Capacitance: 150nF  (hidden comment: *)
Capacitor, Ceramic (MLCC), 150nF, ±10%, 50V, X7R, ±10%, SMD 0603; Manufacturer: Murata Electronics; Manufacturer Part Number: GCM188R71H154KA64D
footprint CAP-0603 (0603 (1608M) Capacitor)
pins: 1, 2

## GCM188R71H222JA37D
designator C?  Capacitance: 2.2nF  (hidden comment: *)
Capacitor, Ceramic (MLCC), 2.2nF, ±5%, 50V, X7R, ±5%, SMD 0603; Manufacturer: Murata Electronics; Manufacturer Part Number: GCM188R71H222JA37D
footprint CAP-0603 (0603 (1608M) Capacitor)
pins: 1, 2

## GCM188R71H223JA37D
designator C?  Capacitance: 22nF  (hidden comment: *)
Capacitor, Ceramic (MLCC), 22nF, ±5%, 50V, X7R, ±5%, SMD 0603; Manufacturer: Murata Electronics; Manufacturer Part Number: GCM188R71H223JA37D
footprint CAP-0603 (0603 (1608M) Capacitor)
pins: 1, 2

## GCM188R71H224KA64D
designator C?  Capacitance: 220nF  (hidden comment: *)
Capacitor, Ceramic (MLCC), 220nF, ±10%, 50V, X7R, ±10%, SMD 0603; Manufacturer: Murata Electronics; Manufacturer Part Number: GCM188R71H224KA64D
footprint CAP-0603 (0603 (1608M) Capacitor)
pins: 1, 2

## GCM188R71H272KA37D
designator C?  Capacitance: 2.7nF  (hidden comment: *)
Capacitor, Ceramic (MLCC), 2.7nF, ±10%, 50V, X7R, ±10%, SMD 0603; Manufacturer: Murata Electronics; Manufacturer Part Number: GCM188R71H272KA37D
footprint CAP-0603 (0603 (1608M) Capacitor)
pins: 1, 2

## GCM188R71H273KA55J
designator C?  Capacitance: 27nF  (hidden comment: *)
Capacitor, Ceramic (MLCC), 27nF, ±10%, 50V, X7R, ±10%, SMD 0603; Manufacturer: Murata Electronics; Manufacturer Part Number: GCM188R71H273KA55J
footprint CAP-0603 (0603 (1608M) Capacitor)
pins: 1, 2

## GCM188R71H682KA37D
designator C?  Capacitance: 6.8nF  (hidden comment: *)
Capacitor, Ceramic (MLCC), 6.8nF, ±10%, 50V, X7R, ±10%, SMD 0603; Manufacturer: Murata Electronics; Manufacturer Part Number: GCM188R71H682KA37D
footprint CAP-0603 (0603 (1608M) Capacitor)
pins: 1, 2

## GCM188R72A102KA37D
designator C?  Capacitance: 1nF  (hidden comment: *)
Capacitor, Ceramic (MLCC), 1nF, ±10%, 100V, X7R, ±10%, SMD 0603; Manufacturer: Murata Electronics; Manufacturer Part Number: GCM188R72A102KA37D
footprint CAP-0603 (0603 (1608M) Capacitor)
pins: 1, 2

## GCM188R72A103KA37D
designator C?  Capacitance: 10nF  (hidden comment: *)
Capacitor, Ceramic (MLCC), 10nF, ±10%, 100V, X7R, ±10%, SMD 0603; Manufacturer: Murata Electronics; Manufacturer Part Number: GCM188R72A103KA37D
footprint CAP-0603 (0603 (1608M) Capacitor)
pins: 1, 2

## GCM188R72A104KA64D
designator C?  Capacitance: 100nF  (hidden comment: *)
Capacitor, Ceramic (MLCC), 100nF, ±10%, 100V, X7R, ±10%, SMD 0603; Manufacturer: Murata Electronics; Manufacturer Part Number: GCM188R72A104KA64D
footprint CAP-0603 (0603 (1608M) Capacitor)
pins: 1, 2

## GCM188R72A153KA37D
designator C?  Capacitance: 15nF  (hidden comment: *)
Capacitor, Ceramic (MLCC), 15nF, ±10%, 100V, X7R, ±10%, SMD 0603; Manufacturer: Murata Electronics; Manufacturer Part Number: GCM188R72A153KA37D
footprint CAP-0603 (0603 (1608M) Capacitor)
pins: 1, 2

## GCM188R72A222KA37D
designator C?  Capacitance: 2.2nF  (hidden comment: *)
Capacitor, Ceramic (MLCC), 2.2nF, ±10%, 100V, X7R, ±10%, SMD 0603; Manufacturer: Murata Electronics; Manufacturer Part Number: GCM188R72A222KA37D
footprint CAP-0603 (0603 (1608M) Capacitor)
pins: 1, 2

## GCM188R72A223KA37D
designator C?  Capacitance: 22nF  (hidden comment: *)
Capacitor, Ceramic (MLCC), 22nF, ±10%, 100V, X7R, ±10%, SMD 0603; Manufacturer: Murata Electronics; Manufacturer Part Number: GCM188R72A223KA37D
footprint CAP-0603 (0603 (1608M) Capacitor)
pins: 1, 2

## GCM188R72A472KA37D
designator C?  Capacitance: 4.7nF  (hidden comment: *)
Capacitor, Ceramic (MLCC), 4.7nF, ±10%, 100V, X7R, ±10%, SMD 0603; Manufacturer: Murata Electronics; Manufacturer Part Number: GCM188R72A472KA37D
footprint CAP-0603 (0603 (1608M) Capacitor)
pins: 1, 2

## GCM188R72A682KA37D
designator C?  Capacitance: 6.8nF  (hidden comment: *)
Capacitor, Ceramic (MLCC), 6.8nF, ±10%, ±10%, SMD 0603; Manufacturer: Murata Electronics; Manufacturer Part Number: GCM188R72A682KA37D
footprint CAP-0603 (0603 (1608M) Capacitor)
pins: 1, 2

## GCM188R91E104KA37D
designator C?  Capacitance: 100nF  (hidden comment: *)
Capacitor, Ceramic (MLCC), 100nF, ±10%, ±10%, SMD 0603; Manufacturer: Murata Electronics; Manufacturer Part Number: GCM188R91E104KA37D
footprint CAP-0603 (0603 (1608M) Capacitor)
pins: 1, 2

## GCM188R91H102KA37D
designator C?  Capacitance: 1nF  (hidden comment: *)
Capacitor, Ceramic (MLCC), 1nF, ±10%, 50V, X8R, ±10%, SMD 0603; Manufacturer: Murata Electronics; Manufacturer Part Number: GCM188R91H102KA37D
footprint CAP-0603 (0603 (1608M) Capacitor)
pins: 1, 2

## GCM188R91H472KA37D
designator C?  Capacitance: 4.7nF  (hidden comment: *)
Capacitor, Ceramic (MLCC), 4.7nF, ±10%, 50V, X8R, ±10%, SMD 0603; Manufacturer: Murata Electronics; Manufacturer Part Number: GCM188R91H472KA37D
footprint CAP-0603 (0603 (1608M) Capacitor)
pins: 1, 2

## GCM1882C1H221JA01D
designator C?  Capacitance: 220pF  (hidden comment: *)
Capacitor, Ceramic (MLCC), 220pF, ±5%, 50V, CH, ±5%, SMD 0603; Manufacturer: Murata Electronics; Manufacturer Part Number: GCM1882C1H221JA01D
footprint CAP-0603 (0603 (1608M) Capacitor)
pins: 1, 2

## GCM1885C1H1R0BA16D
designator C?  Capacitance: 1pF  (hidden comment: *)
Capacitor, Ceramic (MLCC), 1pF, ±0.1pF, 50V, C0G, ±0.1pF, SMD 0603; Manufacturer: Murata Electronics; Manufacturer Part Number: GCM1885C1H1R0BA16D
footprint CAP-0603 (0603 (1608M) Capacitor)
pins: 1, 2

## GCM1885C1H1R8BA16D
designator C?  Capacitance: 1.8pF  (hidden comment: *)
Capacitor, Ceramic (MLCC), 1.8pF, ±0.1pF, 50V, C0G, ±0.1pF, SMD 0603; Manufacturer: Murata Electronics; Manufacturer Part Number: GCM1885C1H1R8BA16D
footprint CAP-0603 (0603 (1608M) Capacitor)
pins: 1, 2

## GCM1885C1H1R8CA16D
designator C?  Capacitance: 1.8pF  (hidden comment: *)
Capacitor, Ceramic (MLCC), 1.8pF, ±0.25pF, 50V, C0G, ±0.25pF, SMD 0603; Manufacturer: Murata Electronics; Manufacturer Part Number: GCM1885C1H1R8CA16D
footprint CAP-0603 (0603 (1608M) Capacitor)
pins: 1, 2

## GCM1885C1H2R0CA16D
designator C?  Capacitance: 2pF  (hidden comment: *)
Capacitor, Ceramic (MLCC), 2pF, ±0.25pF, 50V, C0G, ±0.25pF, SMD 0603; Manufacturer: Murata Electronics; Manufacturer Part Number: GCM1885C1H2R0CA16D
footprint CAP-0603 (0603 (1608M) Capacitor)
pins: 1, 2

## GCM1885C1H4R7CA16D
designator C?  Capacitance: 4.7pF  (hidden comment: *)
Capacitor, Ceramic (MLCC), 4.7pF, ±0.25pF, 50V, ±0.25pF, SMD 0603; Manufacturer: Murata Electronics; Manufacturer Part Number: GCM1885C1H4R7CA16D
footprint CAP-0603 (0603 (1608M) Capacitor)
pins: 1, 2

## GCM1885C1H5R0CA16D
designator C?  Capacitance: 5pF  (hidden comment: *)
Capacitor, Ceramic (MLCC), 5pF, ±0.25pF, 50V, C0G, ±0.25pF, SMD 0603; Manufacturer: Murata Electronics; Manufacturer Part Number: GCM1885C1H5R0CA16D
footprint CAP-0603 (0603 (1608M) Capacitor)
pins: 1, 2

## GCM1885C1H6R0CA16D
designator C?  Capacitance: 6pF  (hidden comment: *)
Capacitor, Ceramic (MLCC), 6pF, ±0.25pF, 50V, C0G, ±0.25pF, SMD 0603; Manufacturer: Murata Electronics; Manufacturer Part Number: GCM1885C1H6R0CA16D
footprint CAP-0603 (0603 (1608M) Capacitor)
pins: 1, 2

## GCM1885C1H6R8CA16D
designator C?  Capacitance: 6.8pF  (hidden comment: *)
Capacitor, Ceramic (MLCC), 6.8pF, ±0.25pF, 50V, C0G, ±0.25pF, SMD 0603; Manufacturer: Murata Electronics; Manufacturer Part Number: GCM1885C1H6R8CA16D
footprint CAP-0603 (0603 (1608M) Capacitor)
pins: 1, 2

## GCM1885C1H8R0CA16D
designator C?  Capacitance: 8pF  (hidden comment: *)
Capacitor, Ceramic (MLCC), 8pF, ±0.25pF, 50V, C0G, ±0.25pF, SMD 0603; Manufacturer: Murata Electronics; Manufacturer Part Number: GCM1885C1H8R0CA16D
footprint CAP-0603 (0603 (1608M) Capacitor)
pins: 1, 2

## GCM1885C1H9R0BA16D
designator C?  Capacitance: 9pF  (hidden comment: *)
Capacitor, Ceramic (MLCC), 9pF, ±0.1pF, 50V, C0G, ±0.1pF, SMD 0603; Manufacturer: Murata Electronics; Manufacturer Part Number: GCM1885C1H9R0BA16D
footprint CAP-0603 (0603 (1608M) Capacitor)
pins: 1, 2

## GCM1885C1H120FA16D
designator C?  Capacitance: 12pF  (hidden comment: *)
Capacitor, Ceramic (MLCC), 12pF, ±1%, 50V, C0G, ±1%, SMD 0603; Manufacturer: Murata Electronics; Manufacturer Part Number: GCM1885C1H120FA16D
footprint CAP-0603 (0603 (1608M) Capacitor)
pins: 1, 2

## GCM1885C1H120JA16D
designator C?  Capacitance: 12pF  (hidden comment: *)
Capacitor, Ceramic (MLCC), 12pF, ±5%, 50V, C0G, ±5%, SMD 0603; Manufacturer: Murata Electronics; Manufacturer Part Number: GCM1885C1H120JA16D
footprint CAP-0603 (0603 (1608M) Capacitor)
pins: 1, 2

## GCM1885C1H121JA16D
designator C?  Capacitance: 120pF  (hidden comment: *)
Capacitor, Ceramic (MLCC), 120pF, ±5%, 50V, C0G, ±5%, SMD 0603; Manufacturer: Murata Electronics; Manufacturer Part Number: GCM1885C1H121JA16D
footprint CAP-0603 (0603 (1608M) Capacitor)
pins: 1, 2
